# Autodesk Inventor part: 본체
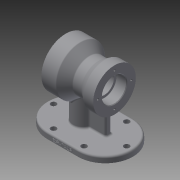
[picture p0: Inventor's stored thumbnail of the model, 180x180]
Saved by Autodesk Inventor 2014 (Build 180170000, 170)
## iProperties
Created: 2020-01
Part Number: 본체
Material: Generic
Document SubType Name: Modeling
Designer: kh
Density: 1 g/cm^3
Appearance: Default
Author: kh
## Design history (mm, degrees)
sketch "Sketch3"
  geometry: L1 (-25, -45)-(25, -45); L2 (70, 0)-(70, 0); L3 (25, 45)-(-25, 45); L4 (-70, 0)-(-70, 0); L5 (-70, -45)-(70, 45); L6 (70, -45)-(-70, 45); A1 r 45 centre (-25, 0) between (-25, 45) and (-70, 0); A2 r 45 centre (-25, 0) between (-70, 0) and (-25, -45); A3 r 45 centre (25, 0) between (25, -45) and (70, 0); A4 r 45 centre (25, 0) between (70, 0) and (25, 45); 1 further point
  constraints: 12 end point, 8 point on circle, 8 point on line, 8 tangent, 4 centre point, 3 equal radius, 2 midpoint, 2 parallel, 1 horizontal, 1 perpendicular
  dimensions: "d4" = 140 distance of L5.end L6.end; "d5" = 90 distance of L6.start L5.end; "d6" = 45 radius of A1; "d7" = 50 distance of A3.centre A1.centre (derived)
extrude "Extrusion2" new body sketch "Sketch3" distance "d8" = 10; taper "d9" = 0 deg
sketch "Sketch4"
  geometry: C1 r 16 at (-12, 0); A1 r 45 centre (-25, 0) between (-25, 45) and (-25, -45) reference; 2 further points
  constraints: 1 centre point, 1 horizontal alignment, 1 point on circle
  dimensions: "d10" = 32 diameter of C1; "d11" = 58 distance of point (-70, 0) C1.centre
extrude "Extrusion3" join sketch "Sketch4" distance "d12" = 70; taper "d13" = 0 deg
sketch "Sketch5"
  geometry: L1 (-40, 80)-(67.661, 80); L2 (40, 80)-(40, 120); L3 (40, 120)-(16, 120); L4 (16, 120)-(1.103, 107.5); L5 (1.103, 107.5)-(-13.289, 107.5); L6 (-13.289, 107.5)-(-24, 115); L7 (-24, 115)-(-40, 115); L8 (-40, 115)-(-40, 80); L9 (70, 0)-(70, 10) reference; 1 further point
  constraints: 16 end point, 3 parallel, 2 perpendicular, 1 horizontal, 1 point on line
  dimensions: "d14" = 80 distance from line of point (0, 0) L1; "d15" = 80 diameter of L3 L1; "d16" = 70 diameter of L7 L1; "d17" = 16 distance of L6.end L7.end; "d18" = 24 distance of L2.end L3.end; "d19" = 80 distance between parallel lines of L8 L2; "d20" = 40 deg angle of L4 L5; "d21" = 35 deg angle of L5 L6; "d22" = 30 distance between parallel lines of L9 L2; "d23" = 55 diameter of L5 L1
revolve "Revolution1" sketch "Sketch5" stored, may be unused: angle "d24" = 90 deg
sketch "Sketch6"
  geometry: L1 (-30, 68.236)-(-30, 5.842); L2 (-40, 45)-(-40, 115) reference; L3 (-4, 10)-(-4, 52.5) reference; 1 further point
  constraints: 2 end point, 1 vertical
  dimensions: "d25" = 10 distance between parallel lines of L2 L1
feature "Rib1" sketch "Sketch6" dims "d26" = 1, "d27" = 10, "d28" = 0, "d29" = 0, "d30" = 1, "d31" = 1
sketch "Sketch7"
  geometry: L1 (-40, 45)-(-40, 115) reference; L2 (40, 40)-(40, 120) reference; L3 (40, 80)-(-40, 80); L4 (40, 80)-(40, 106); L5 (40, 106)-(20.3, 106); L6 (20, 105.7)-(20, 96); L7 (20, 96)-(-23, 96); L8 (-23, 96)-(-23, 99.7); L9 (-23.3, 100)-(-40, 100); L10 (-40, 100)-(-40, 80); A1 r 0.3 centre (-23.3, 99.7) between (-23, 99.7) and (-23.3, 100); A2 r 0.3 centre (20.3, 105.7) between (20.3, 106) and (20, 105.7); 3 further points
  constraints: 16 end point, 6 point on line, 4 point on circle, 4 tangent, 3 perpendicular, 2 centre point, 2 midpoint, 2 parallel, 1 collinear, 1 equal radius
  dimensions: "d32" = 52 diameter of L5 L3; "d33" = 32 diameter of L7 L3; "d34" = 40 diameter of L9 L3; "d35" = 20 distance of L4.end point (20, 106); "d36" = 17 distance of point (-23, 100) L9.end; "d37" = 0.3 radius of A1
revolve "Revolution2" sketch "Sketch7" stored, may be unused: angle "d38" = 90 deg
sketch "Sketch8"
  geometry: C1 r 20 at (0, 0) reference; 2 further points
  constraints: 1 horizontal alignment
  dimensions: "d39" = 27.5 distance of C1.centre point (-27.5, 0)
hole "Hole1" sketch "Sketch8" at (-27.5, 0) diameter "d40" = 3.242; stored, may be unused: countersink angle "d44" = 90 deg, drill point angle "d46" = 118 deg; dims "d41" = 9, "d42" = 4, "d43" = 2, "d45" = 11
pattern_circular "Circular Pattern1" dims angle "d48" = 360 deg
sketch "Sketch9"
  geometry: C1 r 26 at (0, 0) reference; 2 further points
  constraints: 1 horizontal alignment
  dimensions: "d50" = 33 distance of C1.centre point (33, 0)
hole "Hole2" sketch "Sketch9" at (33, 0) diameter "d51" = 3.242; stored, may be unused: countersink angle "d55" = 90 deg, drill point angle "d57" = 118 deg; dims "d52" = 9, "d53" = 4, "d54" = 2, "d56" = 11
pattern_circular "Circular Pattern2" dims angle "d59" = 360 deg
sketch "Sketch10"
  geometry: L1 (25, 45)-(-25, 45) reference; L2 (30, -5)-(3.199, -5) reference; L3 (-25, 0)-(25, 0); L4 (-25, -35)-(25, -35); L5 (25, 35)-(-25, 35); A1 r 45 centre (-25, 0) between (-25, 45) and (-25, -45) reference; A2 r 45 centre (25, 0) between (25, -45) and (25, 45) reference; A3 r 35 centre (-25, 0) between (-25, 35) and (-25, -35); A4 r 35 centre (25, 0) between (25, -35) and (25, 35); 8 further points
  constraints: 8 end point, 8 point on circle, 4 tangent, 2 centre point, 2 parallel, 2 vertical alignment, 1 coincident, 1 midpoint, 1 point on line
  dimensions: "d61" = 10 distance between parallel lines of L5 L1; "d62" = 50 distance of point (25, 35) point (-25, 35)
hole "Hole3" sketch "Sketch10" at (-60, 0), (60, 0), (-25, 35), (25, 35), (25, -35), (-25, -35) diameter "d63" = 9; stored, may be unused: countersink angle "d67" = 90 deg, drill point angle "d69" = 118 deg; dims "d64" = 9, "d65" = 4, "d66" = 2, "d68" = 12
sketch "Sketch11"
  geometry: L1 (-45, 0)-(-45, 10) reference; 2 further points
  constraints: 1 other
  dimensions: "d70" = 70 distance from line of L1 point (25, 4); "d71" = 4 distance of point (25, 0) point (25, 4)
emboss "Emboss1" sketch "Sketch11" dims "d4" = 140, "d5" = 90, "d6" = 45, "d7" = 50 (derived), "d72" = 0.5, "d73" = 0
fillet "Fillet1" dims "d74" = 3, "d75" = 3, "d76" = 2
chamfer "Chamfer1" distance "d77" = 1; stored, may be unused: second distance "d78" = 2, angle "d79" = 45 deg
body "Solid2"
